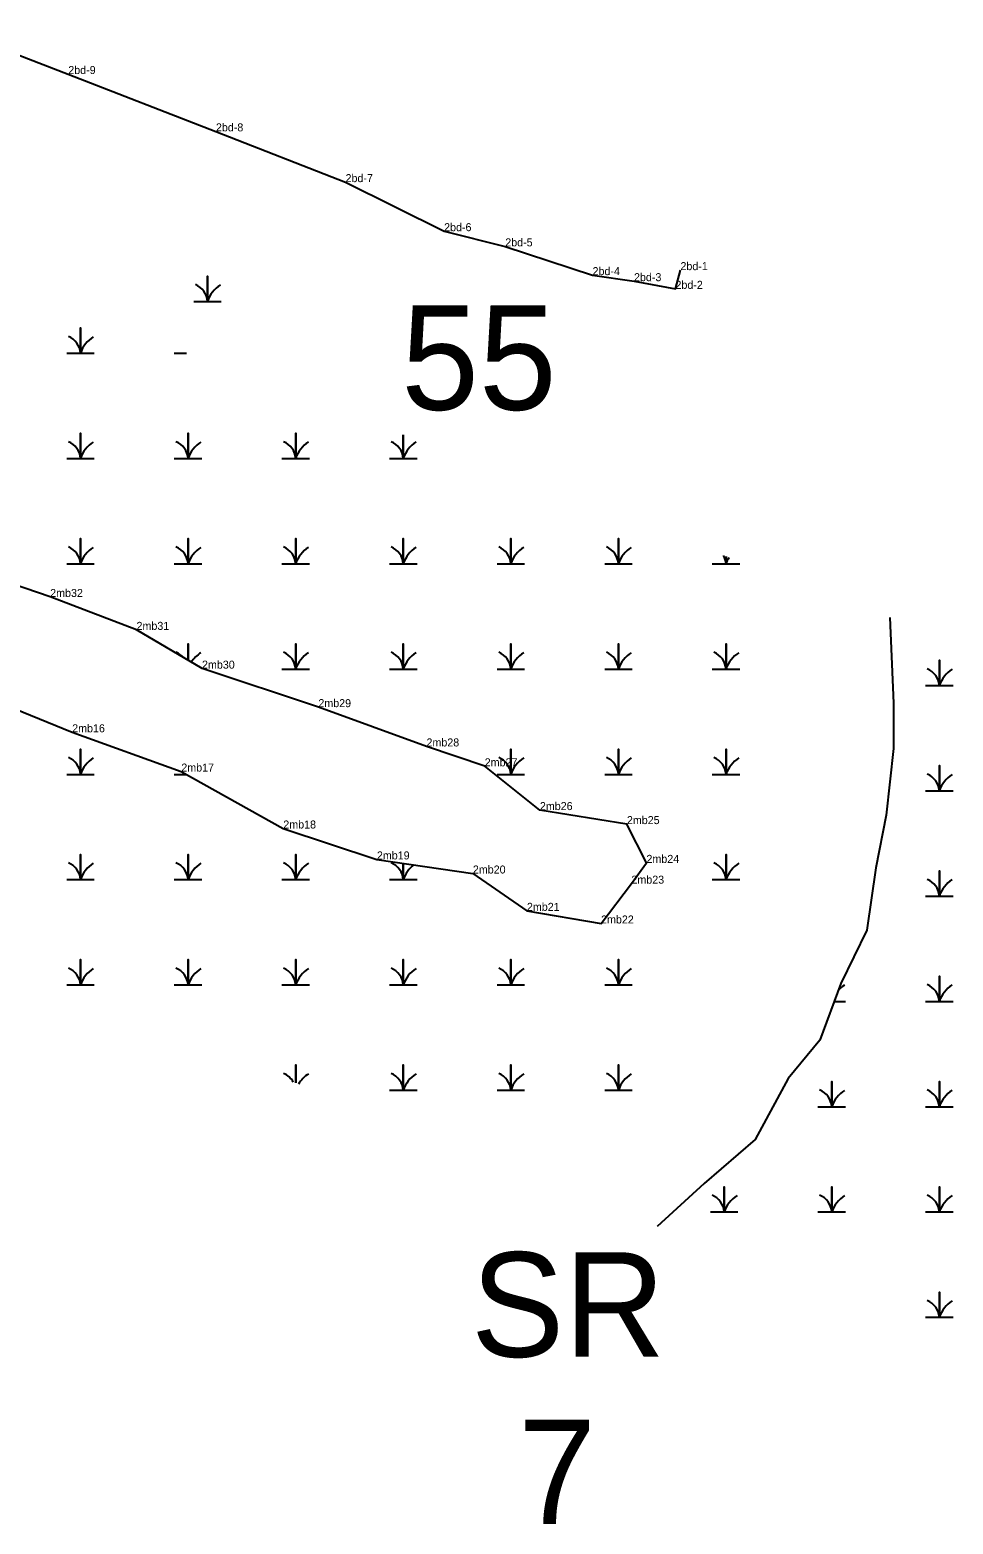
# Model space of a CAD drawing. Extents: x 2072529 to 2268796, y 436423 to 470406.
# Drawn here: x 2105472 to 2106049, y 454077 to 455011 of the extents above; entities that cross this region are included whole.
import ezdxf

# ---------------------------------------------------------------- set-up
doc = ezdxf.new("R2010")
doc.units = 0
for name, color, linetype in [('Default', 7, 'Continuous'), ('Exist Environmental Wetland Boundary Cogo Comment', 7, 'Continuous'), ('Exist Environmental Wetland Boundary Cogo Point CELL', 7, 'Continuous'), ('Old_Level_20', 7, 'Continuous'), ('Old_Level_52', 7, 'Continuous')]:
    doc.layers.add(name, color=color, linetype=linetype)

msp = doc.modelspace()

# ---------------------------------------------------------------- linework, layer by layer
at = {"layer": 'Exist Environmental Wetland Boundary Cogo Point CELL'}
msp.add_line((2105582.94, 454848.14), (2105582.94, 454848.14), dxfattribs=at)
for points in [[(2105574.34, 454841.01), (2105582.94, 454841.01), (2105582.94, 454856.79), (2105582.94, 454841.01), (2105591.54, 454841.01)], [(2105494.95, 454808.64), (2105503.55, 454808.64), (2105503.55, 454824.42), (2105503.55, 454808.64), (2105512.15, 454808.64)], [(2105562.2, 454808.64), (2105569.79, 454808.64)], [(2105494.95, 454742.84), (2105503.55, 454742.84), (2105503.55, 454758.62), (2105503.55, 454742.84), (2105512.15, 454742.84)], [(2105562.2, 454742.84), (2105570.8, 454742.84), (2105570.8, 454758.62), (2105570.8, 454742.84), (2105579.4, 454742.84)], [(2105629.45, 454742.84), (2105638.05, 454742.84), (2105638.05, 454758.62), (2105638.05, 454742.84), (2105646.65, 454742.84)], [(2105696.7, 454742.84), (2105705.3, 454742.84), (2105705.3, 454757.61)], [(2105705.3, 454757.61), (2105705.3, 454742.84), (2105713.9, 454742.84)], [(2105494.95, 454677.04), (2105503.55, 454677.04), (2105503.55, 454692.82), (2105503.55, 454677.04), (2105512.15, 454677.04)], [(2105562.2, 454677.04), (2105570.8, 454677.04), (2105570.8, 454692.82), (2105570.8, 454677.04), (2105579.4, 454677.04)], [(2105629.45, 454677.04), (2105638.05, 454677.04), (2105638.05, 454692.82), (2105638.05, 454677.04), (2105646.65, 454677.04)], [(2105696.7, 454677.04), (2105705.3, 454677.04), (2105705.3, 454692.82), (2105705.3, 454677.04), (2105713.9, 454677.04)], [(2105763.95, 454677.04), (2105772.55, 454677.04), (2105772.55, 454692.82), (2105772.55, 454677.04), (2105781.15, 454677.04)], [(2105831.2, 454677.04), (2105839.8, 454677.04), (2105839.8, 454692.82), (2105839.8, 454677.04), (2105848.4, 454677.04)], [(2105898.45, 454677.04), (2105907.05, 454677.04), (2105907.05, 454681.62)], [(2105907.05, 454681.62), (2105907.05, 454677.04), (2105915.65, 454677.04)], [(2105570.8, 454616.64), (2105570.8, 454627.02), (2105570.8, 454616.64)], [(2105629.45, 454611.24), (2105638.05, 454611.24), (2105638.05, 454627.02), (2105638.05, 454611.24), (2105646.65, 454611.24)], [(2105696.7, 454611.24), (2105705.3, 454611.24), (2105705.3, 454627.02), (2105705.3, 454611.24), (2105713.9, 454611.24)], [(2105763.95, 454611.24), (2105772.55, 454611.24), (2105772.55, 454627.02), (2105772.55, 454611.24), (2105781.15, 454611.24)], [(2105831.2, 454611.24), (2105839.8, 454611.24), (2105839.8, 454627.02), (2105839.8, 454611.24), (2105848.4, 454611.24)], [(2105898.45, 454611.24), (2105907.05, 454611.24), (2105907.05, 454627.02), (2105907.05, 454611.24), (2105915.65, 454611.24)], [(2106031.78, 454600.93), (2106040.39, 454600.93), (2106040.39, 454616.71), (2106040.39, 454600.93), (2106048.99, 454600.93)], [(2105494.95, 454545.44), (2105503.55, 454545.44), (2105503.55, 454561.22), (2105503.55, 454545.44), (2105512.15, 454545.44)], [(2105763.95, 454545.44), (2105772.55, 454545.44), (2105772.55, 454561.22), (2105772.55, 454545.44), (2105781.15, 454545.44)], [(2105831.2, 454545.44), (2105839.8, 454545.44), (2105839.8, 454561.22), (2105839.8, 454545.44), (2105848.4, 454545.44)], [(2105898.45, 454545.44), (2105907.05, 454545.44), (2105907.05, 454561.22), (2105907.05, 454545.44), (2105915.65, 454545.44)], [(2106031.78, 454535.13), (2106040.39, 454535.13), (2106040.39, 454550.91), (2106040.39, 454535.13), (2106048.99, 454535.13)], [(2105562.2, 454545.44), (2105569.67, 454545.44)], [(2105494.95, 454479.64), (2105503.55, 454479.64), (2105503.55, 454495.42), (2105503.55, 454479.64), (2105512.15, 454479.64)], [(2105562.2, 454479.64), (2105570.8, 454479.64), (2105570.8, 454495.42), (2105570.8, 454479.64), (2105579.4, 454479.64)], [(2105629.45, 454479.64), (2105638.05, 454479.64), (2105638.05, 454495.42), (2105638.05, 454479.64), (2105646.65, 454479.64)], [(2105898.45, 454479.64), (2105907.05, 454479.64), (2105907.05, 454495.42), (2105907.05, 454479.64), (2105915.65, 454479.64)], [(2105696.7, 454479.64), (2105705.3, 454479.64), (2105705.3, 454489.85)], [(2105705.3, 454489.85), (2105705.3, 454479.64), (2105713.9, 454479.64)], [(2106031.78, 454469.33), (2106040.39, 454469.33), (2106040.39, 454485.11), (2106040.39, 454469.33), (2106048.99, 454469.33)], [(2105494.95, 454413.84), (2105503.55, 454413.84), (2105503.55, 454429.62), (2105503.55, 454413.84), (2105512.15, 454413.84)], [(2105562.2, 454413.84), (2105570.8, 454413.84), (2105570.8, 454429.62), (2105570.8, 454413.84), (2105579.4, 454413.84)], [(2105629.45, 454413.84), (2105638.05, 454413.84), (2105638.05, 454429.62), (2105638.05, 454413.84), (2105646.65, 454413.84)], [(2105696.7, 454413.84), (2105705.3, 454413.84), (2105705.3, 454429.62), (2105705.3, 454413.84), (2105713.9, 454413.84)], [(2105763.95, 454413.84), (2105772.55, 454413.84), (2105772.55, 454429.62), (2105772.55, 454413.84), (2105781.15, 454413.84)], [(2105831.2, 454413.84), (2105839.8, 454413.84), (2105839.8, 454429.62), (2105839.8, 454413.84), (2105848.4, 454413.84)], [(2106031.78, 454403.53), (2106040.39, 454403.53), (2106040.39, 454419.31), (2106040.39, 454403.53), (2106048.99, 454403.53)], [(2105974.61, 454403.53), (2105981.74, 454403.53)], [(2105638.05, 454352.56), (2105638.05, 454363.82), (2105638.05, 454352.56)], [(2105696.7, 454348.04), (2105705.3, 454348.04), (2105705.3, 454363.82), (2105705.3, 454348.04), (2105713.9, 454348.04)], [(2105763.95, 454348.04), (2105772.55, 454348.04), (2105772.55, 454363.82), (2105772.55, 454348.04), (2105781.15, 454348.04)], [(2105831.2, 454348.04), (2105839.8, 454348.04), (2105839.8, 454363.82), (2105839.8, 454348.04), (2105848.4, 454348.04)], [(2105964.53, 454337.73), (2105973.14, 454337.73), (2105973.14, 454353.51), (2105973.14, 454337.73), (2105981.74, 454337.73)], [(2106031.78, 454337.73), (2106040.39, 454337.73), (2106040.39, 454353.51), (2106040.39, 454337.73), (2106048.99, 454337.73)], [(2105897.28, 454271.93), (2105905.89, 454271.93), (2105905.89, 454287.71), (2105905.89, 454271.93), (2105914.49, 454271.93)], [(2105964.53, 454271.93), (2105973.14, 454271.93), (2105973.14, 454287.71), (2105973.14, 454271.93), (2105981.74, 454271.93)], [(2106031.78, 454271.93), (2106040.39, 454271.93), (2106040.39, 454287.71), (2106040.39, 454271.93), (2106048.99, 454271.93)], [(2106031.78, 454206.13), (2106040.39, 454206.13), (2106040.39, 454221.91), (2106040.39, 454206.13), (2106048.99, 454206.13)]]:
    msp.add_lwpolyline(points, dxfattribs=at)
for centre, radius, start, end in [((2105570.67, 454840.12), 12.3, 4.14034, 67.53497), ((2105601.18, 454834.95), 19.22, 122.12745, 161.62219), ((2105491.28, 454807.76), 12.3, 4.14034, 67.53497), ((2105521.79, 454802.58), 19.22, 122.12745, 161.62219), ((2105491.28, 454741.96), 12.3, 4.14034, 67.53497), ((2105558.53, 454741.96), 12.3, 4.14034, 67.53497), ((2105625.78, 454741.96), 12.3, 4.14034, 67.53497), ((2105693.03, 454741.96), 12.3, 4.14034, 67.53497), ((2105521.79, 454736.78), 19.22, 122.12745, 161.62219), ((2105589.04, 454736.78), 19.22, 122.12745, 161.62219), ((2105656.29, 454736.78), 19.22, 122.12745, 161.62219), ((2105723.54, 454736.78), 19.22, 122.12745, 161.62219), ((2105491.28, 454676.16), 12.3, 4.14034, 67.53497), ((2105521.79, 454670.98), 19.22, 122.12745, 161.62219), ((2105558.53, 454676.16), 12.3, 4.14034, 67.53497), ((2105589.04, 454670.98), 19.22, 122.12745, 161.62219), ((2105625.78, 454676.16), 12.3, 4.14034, 67.53497), ((2105656.29, 454670.98), 19.22, 122.12745, 161.62219), ((2105693.03, 454676.16), 12.3, 4.14034, 67.53497), ((2105723.54, 454670.98), 19.22, 122.12745, 161.62219), ((2105760.28, 454676.16), 12.3, 4.14034, 67.53497), ((2105790.79, 454670.98), 19.22, 122.12745, 161.62219), ((2105827.53, 454676.16), 12.3, 4.14034, 67.53497), ((2105858.04, 454670.98), 19.22, 122.12745, 161.62219), ((2105894.78, 454676.16), 12.3, 4.14034, 29.50947), ((2105925.29, 454670.98), 19.22, 148.78323, 161.62219), ((2105558.53, 454610.36), 12.3, 40.84562, 67.53497), ((2105589.04, 454605.18), 19.22, 122.12745, 147.67873), ((2105625.78, 454610.36), 12.3, 4.14034, 67.53497), ((2105656.29, 454605.18), 19.22, 122.12745, 161.62219), ((2105693.03, 454610.36), 12.3, 4.14034, 67.53497), ((2105723.54, 454605.18), 19.22, 122.12745, 161.62219), ((2105760.28, 454610.36), 12.3, 4.14034, 67.53497), ((2105790.79, 454605.18), 19.22, 122.12745, 161.62219), ((2105827.53, 454610.36), 12.3, 4.14034, 67.53497), ((2105858.04, 454605.18), 19.22, 122.12745, 161.62219), ((2105894.78, 454610.36), 12.3, 4.14034, 67.53497), ((2105925.29, 454605.18), 19.22, 122.12745, 161.62219), ((2106028.12, 454600.04), 12.3, 4.14034, 67.53497), ((2106058.63, 454594.86), 19.22, 122.12745, 161.62219), ((2105491.28, 454544.56), 12.3, 4.14034, 67.53497), ((2105521.79, 454539.38), 19.22, 122.12745, 161.62219), ((2105760.28, 454544.56), 12.3, 4.14034, 67.53497), ((2105790.79, 454539.38), 19.22, 122.12745, 161.62219), ((2105827.53, 454544.56), 12.3, 4.14034, 67.53497), ((2105858.04, 454539.38), 19.22, 122.12745, 161.62219), ((2105894.78, 454544.56), 12.3, 4.14034, 67.53497), ((2105925.29, 454539.38), 19.22, 122.12745, 161.62219), ((2106028.12, 454534.24), 12.3, 4.14034, 67.53497), ((2106058.63, 454529.06), 19.22, 122.12745, 161.62219), ((2105491.28, 454478.76), 12.3, 4.14034, 67.53497), ((2105521.79, 454473.58), 19.22, 122.12745, 161.62219), ((2105558.53, 454478.76), 12.3, 4.14034, 67.53497), ((2105589.04, 454473.58), 19.22, 122.12745, 161.62219), ((2105625.78, 454478.76), 12.3, 4.14034, 67.53497), ((2105656.29, 454473.58), 19.22, 122.12745, 161.62219), ((2105693.03, 454478.76), 12.3, 4.14034, 67.53497), ((2105723.54, 454473.58), 19.22, 127.26595, 161.62219), ((2105894.78, 454478.76), 12.3, 4.14034, 67.53497), ((2105925.29, 454473.58), 19.22, 122.12745, 161.62219), ((2106028.12, 454468.44), 12.3, 4.14034, 67.53497), ((2106058.63, 454463.26), 19.22, 122.12745, 161.62219), ((2105491.28, 454412.96), 12.3, 4.14034, 67.53497), ((2105521.79, 454407.78), 19.22, 122.12745, 161.62219), ((2105558.53, 454412.96), 12.3, 4.14034, 67.53497), ((2105589.04, 454407.78), 19.22, 122.12745, 161.62219), ((2105625.78, 454412.96), 12.3, 4.14034, 67.53497), ((2105656.29, 454407.78), 19.22, 122.12745, 161.62219), ((2105693.03, 454412.96), 12.3, 4.14034, 67.53497), ((2105723.54, 454407.78), 19.22, 122.12745, 161.62219), ((2105760.28, 454412.96), 12.3, 4.14034, 67.53497), ((2105790.79, 454407.78), 19.22, 122.12745, 161.62219), ((2105827.53, 454412.96), 12.3, 4.14034, 67.53497), ((2105858.04, 454407.78), 19.22, 122.12745, 161.62219), ((2105991.38, 454397.46), 19.22, 122.12745, 137.58861), ((2106028.12, 454402.64), 12.3, 4.14034, 67.53497), ((2106058.63, 454397.46), 19.22, 122.12745, 161.62219), ((2105625.78, 454347.16), 12.3, 29.0926, 67.53497), ((2105656.29, 454341.98), 19.22, 122.12745, 148.95552), ((2105693.03, 454347.16), 12.3, 4.14034, 67.53497), ((2105723.54, 454341.98), 19.22, 122.12745, 161.62219), ((2105760.28, 454347.16), 12.3, 4.14034, 67.53497), ((2105790.79, 454341.98), 19.22, 122.12745, 161.62219), ((2105827.53, 454347.16), 12.3, 4.14034, 67.53497), ((2105858.04, 454341.98), 19.22, 122.12745, 161.62219), ((2105960.87, 454336.84), 12.3, 4.14034, 67.53497), ((2105991.38, 454331.66), 19.22, 122.12745, 161.62219), ((2106028.12, 454336.84), 12.3, 4.14034, 67.53497), ((2106058.63, 454331.66), 19.22, 122.12745, 161.62219), ((2105893.62, 454271.04), 12.3, 4.14034, 67.53497), ((2105924.13, 454265.86), 19.22, 122.12745, 161.62219), ((2105960.87, 454271.04), 12.3, 4.14034, 67.53497), ((2105991.38, 454265.86), 19.22, 122.12745, 161.62219), ((2106028.12, 454271.04), 12.3, 4.14034, 67.53497), ((2106058.63, 454265.86), 19.22, 122.12745, 161.62219), ((2106028.12, 454205.24), 12.3, 4.14034, 67.53497), ((2106058.63, 454200.06), 19.22, 122.12745, 161.62219)]:
    msp.add_arc(centre, radius, start, end, dxfattribs=at)
at = {"layer": 'Old_Level_20'}
for p, q in [((2105495.92, 454983.09), (2105495.92, 454983.09)), ((2105588.21, 454947.27), (2105588.21, 454947.27)), ((2105669.22, 454915.55), (2105669.22, 454915.55)), ((2105730.84, 454884.87), (2105730.84, 454884.87)), ((2105769.05, 454875.39), (2105769.05, 454875.39)), ((2105823.62, 454857.42), (2105823.62, 454857.42)), ((2105878.55, 454860.54), (2105878.55, 454860.54)), ((2105849.53, 454853.64), (2105849.53, 454853.64)), ((2105875.44, 454848.85), (2105875.44, 454848.85)), ((2105484.6, 454656.29), (2105484.6, 454656.29)), ((2105538.58, 454635.73), (2105538.58, 454635.73)), ((2105579.5, 454611.49), (2105579.5, 454611.49)), ((2105652.23, 454587.43), (2105652.23, 454587.43)), ((2105498.36, 454571.72), (2105498.36, 454571.72)), ((2105719.82, 454562.88), (2105719.82, 454562.88)), ((2105756.21, 454550.47), (2105756.21, 454550.47)), ((2105566.56, 454547.18), (2105566.56, 454547.18)), ((2105790.7, 454523.11), (2105790.7, 454523.11)), ((2105630.31, 454511.59), (2105630.31, 454511.59)), ((2105845.09, 454514.34), (2105845.09, 454514.34)), ((2105688.82, 454492.27), (2105688.82, 454492.27)), ((2105748.81, 454483.46), (2105748.81, 454483.46)), ((2105857.32, 454490.1), (2105857.32, 454490.1)), ((2105847.92, 454477.12), (2105847.92, 454477.12)), ((2105782.59, 454460.13), (2105782.59, 454460.13)), ((2105828.94, 454452.23), (2105828.94, 454452.23))]:
    msp.add_line(p, q, dxfattribs=at)
for points in [[(2105423.92, 455010.69), (2105495.92, 454983.09), (2105588.21, 454947.27), (2105669.22, 454915.55), (2105730.84, 454884.87), (2105769.05, 454875.39), (2105823.62, 454857.42), (2105849.53, 454853.64), (2105875.44, 454848.85), (2105878.55, 454860.54)], [(2105441.4, 454594.88), (2105498.36, 454571.72), (2105566.56, 454547.18), (2105630.31, 454511.59), (2105688.82, 454492.27), (2105748.81, 454483.46), (2105782.59, 454460.13), (2105828.94, 454452.23), (2105847.92, 454477.12), (2105857.32, 454490.1), (2105845.09, 454514.34), (2105790.7, 454523.11), (2105756.21, 454550.47), (2105719.82, 454562.88), (2105652.23, 454587.43), (2105579.5, 454611.49), (2105538.58, 454635.73), (2105484.6, 454656.29), (2105412.52, 454680.85)]]:
    msp.add_lwpolyline(points, dxfattribs=at)
at = {"layer": 'Old_Level_52'}
msp.add_lwpolyline([(2106009.39, 454643.4), (2106011.62, 454590.02), (2106011.62, 454561.52), (2106007.24, 454519.87), (2106000.66, 454486.98), (2105995.03, 454448.1), (2105978.75, 454414.63), (2105965.61, 454379.4), (2105945.89, 454355.44), (2105925.28, 454317.23), (2105893.31, 454289.67), (2105863.9, 454262.91)], dxfattribs=at)

# ---------------------------------------------------------------- texts
at = {"layer": 'Default'}
for s, p in [('55', (2105704, 454773.25)), ('SR', (2105747.65, 454181.41)), ('7', (2105777.21, 454076.86))]:
    msp.add_text(s, height=65.34, dxfattribs=at).set_placement(p)
at = {"layer": 'Exist Environmental Wetland Boundary Cogo Comment'}
for s, p in [('2bd-9', (2105495.92, 454983.09)), ('2bd-8', (2105588.21, 454947.27)), ('2bd-7', (2105669.22, 454915.55)), ('2bd-6', (2105730.84, 454884.87)), ('2bd-5', (2105769.05, 454875.39)), ('2bd-1', (2105878.55, 454860.54)), ('2bd-4', (2105823.62, 454857.42)), ('2bd-3', (2105849.53, 454853.64)), ('2bd-2', (2105875.44, 454848.85)), ('2mb32', (2105484.6, 454656.29)), ('2mb31', (2105538.58, 454635.73)), ('2mb30', (2105579.5, 454611.49)), ('2mb29', (2105652.23, 454587.43)), ('2mb16', (2105498.36, 454571.72)), ('2mb28', (2105719.82, 454562.88)), ('2mb17', (2105566.56, 454547.18)), ('2mb27', (2105756.21, 454550.47)), ('2mb26', (2105790.7, 454523.11)), ('2mb18', (2105630.31, 454511.59)), ('2mb25', (2105845.09, 454514.34)), ('2mb19', (2105688.82, 454492.27)), ('2mb24', (2105857.32, 454490.1)), ('2mb20', (2105748.81, 454483.46)), ('2mb23', (2105847.92, 454477.12)), ('2mb21', (2105782.59, 454460.13)), ('2mb22', (2105828.94, 454452.23))]:
    msp.add_text(s, height=5, dxfattribs=at).set_placement(p)

doc.saveas('drawing.dxf')
